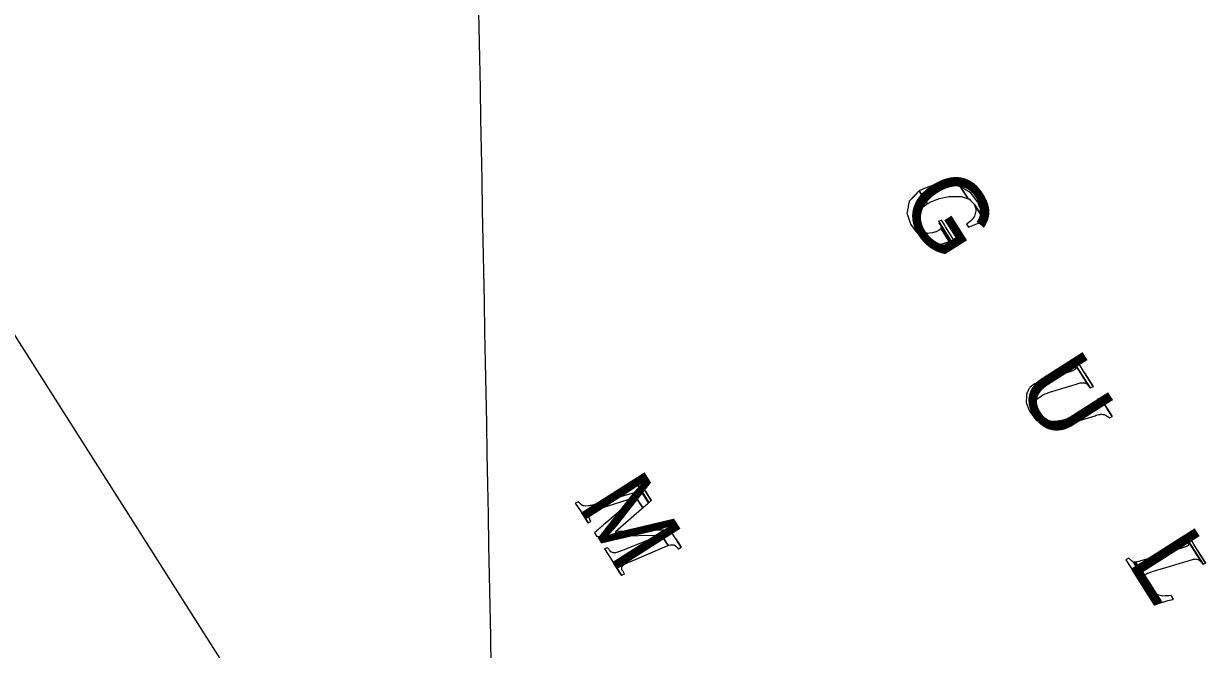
# Model space of a CAD drawing. Extents: x 3962991 to 3983549, y 181631 to 204078.
# Drawn here: x 3972884 to 3974467, y 187232 to 188068 of the extents above; entities that cross this region are included whole.
import ezdxf

# ---------------------------------------------------------------- set-up
doc = ezdxf.new("R2010")
doc.units = 0
for name, color, linetype in [('V-ANNO-MASK', 7, 'Continuous'), ('V-ANNO-MASK2', 7, 'Continuous'), ('V-GRID-FRAM', 7, 'Continuous'), ('V-GRID-MAJR', 7, 'Continuous'), ('V-RIVR-IDEN', 7, 'Continuous')]:
    doc.layers.add(name, color=color, linetype=linetype)

msp = doc.modelspace()

# ---------------------------------------------------------------- linework, layer by layer
at = {"layer": 'V-ANNO-MASK2'}
for points in [[(3974069, 187803.5), (3974070.2, 187799.9), (3974077.6, 187790), (3974084.5, 187783.2), (3974085.5, 187782.4), (3974091.9, 187777.7), (3974077.1, 187800.9), (3974077.1, 187801.3), (3974077, 187802.7), (3974077, 187803.1), (3974076.6, 187812.2), (3974077, 187812.8), (3974078.5, 187814.9), (3974080.7, 187817.8), (3974083.6, 187821.7), (3974083.8, 187821.9), (3974086.9, 187823.9), (3974087.1, 187824), (3974089, 187825.2), (3974089.1, 187825.3), (3974090.4, 187826.1), (3974090.6, 187826.3), (3974091.1, 187826.6), (3974091.4, 187826.8), (3974091.6, 187826.9), (3974091.6, 187826.9), (3974092.1, 187827.3), (3974092.3, 187827.4), (3974092.6, 187827.6), (3974081.6, 187845), (3974081.3, 187844.7), (3974081.1, 187844.5), (3974080.7, 187844.1), (3974080.7, 187844.1), (3974080.5, 187843.9), (3974080.2, 187843.6), (3974079.8, 187843.2), (3974079.7, 187843), (3974078.5, 187841.9), (3974078.5, 187841.8), (3974076.8, 187840.1), (3974076.7, 187839.9), (3974074.1, 187837.2), (3974073.8, 187837), (3974070.6, 187833.7), (3974068.2, 187831.1), (3974067.5, 187827.7), (3974067.3, 187826.8), (3974066.1, 187820.3), (3974066, 187820), (3974065.8, 187819), (3974065.7, 187818.7), (3974065, 187814.7), (3974065.7, 187812.8)], [(3974084.7, 187846.3), (3974081.6, 187845), (3974092.6, 187827.6), (3974095.5, 187829.4), (3974095.5, 187829.5), (3974095.7, 187829.6), (3974095.7, 187829.6), (3974108.6, 187834.5), (3974112.4, 187835.3), (3974121.4, 187837.1), (3974121.4, 187837.1), (3974122.9, 187837.3), (3974129.1, 187837.4), (3974131.2, 187837.4), (3974137.2, 187837.4), (3974138.4, 187837), (3974139, 187836.8), (3974147, 187834.3), (3974136.8, 187850.3), (3974129.3, 187852.1), (3974128.6, 187852.3), (3974127.6, 187852.6), (3974120.4, 187854.3), (3974118.4, 187854.2), (3974112.4, 187853.8), (3974110.9, 187853.7), (3974101.1, 187853), (3974097.7, 187851.6), (3974085, 187846.4), (3974085, 187846.4), (3974084.8, 187846.3)], [(3974137.8, 187849.7), (3974136.8, 187850.3), (3974146.9, 187834.3), (3974147.8, 187834), (3974148.1, 187833.9), (3974150.2, 187831.8), (3974154.8, 187827), (3974155.3, 187826.4), (3974163.7, 187813.2), (3974163.3, 187820.9), (3974162.2, 187823.5), (3974159.6, 187830.2), (3974159.5, 187830.3), (3974150.5, 187842), (3974149.5, 187842.6), (3974142.2, 187847), (3974141.9, 187847.2), (3974139.4, 187848.7), (3974138.3, 187849.4)], [(3974145.8, 187801.2), (3974144.7, 187800.4), (3974147.4, 187796.2), (3974148.7, 187796.8), (3974153.6, 187798.8), (3974155.3, 187799.5), (3974160.1, 187801.4), (3974160.8, 187801.7), (3974161.2, 187801.9), (3974166.3, 187803.9), (3974166.8, 187804.1), (3974167, 187804.2), (3974167.6, 187804.4), (3974163.6, 187810.7), (3974163.8, 187812.8), (3974163.7, 187813.2), (3974155.3, 187826.4), (3974155.4, 187825.9), (3974156.6, 187821.6), (3974157.2, 187819.7), (3974157.4, 187818.9), (3974157.2, 187818.2), (3974155.5, 187810.9), (3974155.2, 187810.6), (3974154.7, 187810), (3974151.3, 187805.7), (3974150.1, 187804.2)], [(3974165.1, 187810.8), (3974163.6, 187810.7), (3974167.6, 187804.4), (3974168.8, 187804.9), (3974172.5, 187806.4), (3974173, 187806.6), (3974173.1, 187806.6), (3974170.1, 187811.2), (3974170, 187811.2), (3974169.4, 187811.2)], [(3974078.8, 187798.6), (3974077.1, 187800.9), (3974091.8, 187777.7), (3974092.3, 187777.3), (3974095.8, 187773.1), (3974096.9, 187771.8), (3974098.6, 187769.2), (3974102.9, 187770.7), (3974103.6, 187771), (3974105.9, 187771.8), (3974109.3, 187772.9), (3974113.6, 187774.5), (3974113.9, 187774.6), (3974113.9, 187774.6), (3974117.5, 187775.8), (3974117.6, 187775.9), (3974120, 187776.5), (3974120.1, 187776.5), (3974122.2, 187776.2), (3974122.6, 187775.9), (3974110.5, 187794.9), (3974110.4, 187794.7), (3974109.5, 187793.2), (3974109.4, 187793.2), (3974107.5, 187791.8), (3974107.4, 187791.7), (3974104, 187790.1), (3974103.7, 187790), (3974099.4, 187788.5), (3974095.5, 187788.1), (3974092.9, 187787.8), (3974091.8, 187788.3), (3974084.6, 187791.2), (3974084.2, 187791.3)], [(3974107.5, 187804.2), (3974107.1, 187804.1), (3974128.6, 187770.3), (3974129, 187770.5), (3974132.1, 187771.8), (3974128.6, 187777.3), (3974121.8, 187788.2), (3974116.7, 187796.5), (3974115.1, 187799.2), (3974111.5, 187805.3), (3974111.2, 187805.2), (3974111.2, 187805.2), (3974111, 187805.2), (3974110.9, 187805.1)], [(3974110.6, 187795.9), (3974110.5, 187794.9), (3974122.6, 187775.9), (3974123.9, 187775.1), (3974125.5, 187773.2), (3974127.8, 187770), (3974127.8, 187770), (3974128.4, 187770.2), (3974128.6, 187770.3), (3974108.3, 187802.2), (3974109.7, 187799.6), (3974110.7, 187796.9), (3974110.7, 187796.8), (3974110.7, 187796.5)], [(3974132.2, 187771.8), (3974128.6, 187777.3), (3974132.1, 187771.8)], [(3974287.1, 187617.8), (3974287, 187617.8), (3974310.1, 187581.5), (3974310.2, 187581.5), (3974313.9, 187583.1), (3974313.9, 187583.1), (3974302.2, 187601.5), (3974291.5, 187619.3), (3974291, 187619.2), (3974291, 187619.1)], [(3974288.3, 187615.4), (3974289.4, 187613.6), (3974307.8, 187584.5), (3974308.4, 187583.8), (3974310, 187581.4), (3974310, 187581.4), (3974310.1, 187581.5), (3974287, 187617.8), (3974288.1, 187615.9)], [(3974227.2, 187554.9), (3974229.1, 187549.7), (3974237.8, 187538.2), (3974240.9, 187536.4), (3974250.2, 187531), (3974238.8, 187549), (3974238.2, 187551.4), (3974238, 187552.1), (3974237.3, 187554.3), (3974236.2, 187558.5), (3974238, 187564.4), (3974238.5, 187565.9), (3974238.9, 187566.9), (3974244.9, 187570.9), (3974246.3, 187571.9), (3974247.5, 187572.7), (3974247.7, 187572.7), (3974258.4, 187576.7), (3974258.6, 187576.7), (3974264.5, 187578.5), (3974266.1, 187579), (3974281, 187583.4), (3974281, 187583.4), (3974290, 187586.1), (3974291.5, 187586.5), (3974291.6, 187586.5), (3974293.3, 187587.1), (3974295.2, 187587.6), (3974296.6, 187588.1), (3974296.7, 187588.1), (3974297.2, 187588.1), (3974298.2, 187588.3), (3974298.6, 187588.3), (3974300, 187588.4), (3974300.7, 187588.4), (3974301.2, 187588.4), (3974301.5, 187588.4), (3974302.9, 187588), (3974303.3, 187588), (3974303.8, 187587.9), (3974304.1, 187587.8), (3974305.4, 187586.9), (3974305.4, 187586.9), (3974305.6, 187586.7), (3974306.3, 187586.3), (3974306.5, 187586.1), (3974307.3, 187585.2), (3974307.9, 187584.5), (3974289.4, 187613.6), (3974289.6, 187613.1), (3974289.8, 187612.4), (3974290, 187611.9), (3974290.5, 187610.6), (3974290.6, 187610.1), (3974290.6, 187608.9), (3974290.6, 187608.6), (3974290.6, 187607.9), (3974290.6, 187607.5), (3974289.9, 187606.7), (3974289.7, 187606.5), (3974289.4, 187606.1), (3974289, 187605.6), (3974287.9, 187605), (3974287.7, 187604.9), (3974286.8, 187604.4), (3974286.4, 187604.2), (3974286.4, 187604.1), (3974285, 187603.6), (3974283.2, 187602.9), (3974281.5, 187602.3), (3974281.5, 187602.3), (3974280, 187601.8), (3974271.1, 187599), (3974256.2, 187594.5), (3974254.7, 187594), (3974248.8, 187592.2), (3974248.6, 187592.1), (3974238, 187588), (3974237.8, 187587.9), (3974236.5, 187587.4), (3974235.1, 187586.3), (3974229.4, 187581.8), (3974228.8, 187581.2), (3974228.1, 187580), (3974225.7, 187575), (3974225, 187573.7), (3974225, 187572.5), (3974224.9, 187572.1), (3974224.9, 187570.9), (3974224.5, 187562.1)], [(3974314.4, 187583.3), (3974302.2, 187601.5), (3974313.9, 187583.1)], [(3974243.8, 187542.5), (3974238.8, 187549), (3974250.2, 187531), (3974251.6, 187530.2), (3974251.8, 187530.3), (3974252.6, 187530.3), (3974254.1, 187530.3), (3974259.7, 187530.4), (3974261, 187530.5), (3974262, 187530.5), (3974270.5, 187530.7), (3974272.2, 187531.2), (3974273.7, 187531.6), (3974273.8, 187531.6), (3974285, 187534.8), (3974285, 187534.8), (3974285.2, 187534.9), (3974291.2, 187536.6), (3974292.8, 187537), (3974307.6, 187541.6), (3974307.6, 187541.6), (3974316.5, 187544.3), (3974318, 187544.8), (3974318, 187544.8), (3974318.1, 187544.8), (3974319.8, 187545.3), (3974321.7, 187545.8), (3974323.4, 187546), (3974323.4, 187546), (3974323.9, 187546.1), (3974325, 187546.2), (3974325.4, 187546.2), (3974326.9, 187546), (3974327.7, 187545.9), (3974328.3, 187545.8), (3974328.6, 187545.8), (3974330.3, 187545), (3974330.7, 187544.9), (3974331.3, 187544.6), (3974331.7, 187544.3), (3974333.1, 187543.4), (3974333.3, 187543.2), (3974334, 187542.8), (3974334.3, 187542.5), (3974334.6, 187542.2), (3974335, 187541.9), (3974335.3, 187541.7), (3974335.3, 187541.6), (3974335.6, 187541.3), (3974335.8, 187541.2), (3974339.2, 187543.3), (3974331.6, 187555.2), (3974330.4, 187557.3), (3974323.7, 187567.8), (3974323.6, 187567.8), (3974319.8, 187566.4), (3974319.7, 187566.4), (3974319.6, 187566.3), (3974319.8, 187566.1), (3974320.3, 187565), (3974320.8, 187563.9), (3974321.1, 187563.2), (3974321.3, 187562.6), (3974321.9, 187561.2), (3974321.9, 187561), (3974322, 187559.6), (3974322.1, 187559.2), (3974322.1, 187558.3), (3974322, 187558), (3974321.5, 187556.8), (3974321.4, 187556.6), (3974321.2, 187556.1), (3974320.8, 187555.7), (3974319.9, 187554.8), (3974319.7, 187554.6), (3974318.9, 187553.9), (3974318.5, 187553.7), (3974318.5, 187553.7), (3974317.2, 187553), (3974315.5, 187552.1), (3974314, 187551.2), (3974314, 187551.2), (3974312.5, 187550.7), (3974303.9, 187547.5), (3974289.1, 187542.7), (3974287.6, 187542.2), (3974281.6, 187540.5), (3974281.4, 187540.5), (3974270.2, 187537.3), (3974270, 187537.3), (3974268.4, 187537.2), (3974266.4, 187537), (3974258.3, 187536.4), (3974257.3, 187536.3), (3974256, 187536.2), (3974248.4, 187539.3), (3974246.3, 187540.2), (3974245.3, 187540.6)], [(3974323.7, 187567.8), (3974323.6, 187567.8), (3974331.6, 187555.2), (3974330.4, 187557.3), (3974324.1, 187568)], [(3974333.3, 187552.7), (3974331.6, 187555.2), (3974339.2, 187543.3), (3974339.2, 187543.4), (3974339.5, 187543.6)], [(3973622.1, 187427.4), (3973621.8, 187427.3), (3973629.6, 187415.6), (3973630.4, 187414.3), (3973638.9, 187401), (3973642.6, 187402.9), (3973641.9, 187404), (3973641.8, 187404.4), (3973641.3, 187405.5), (3973641.1, 187406), (3973640.8, 187406.6), (3973640.8, 187406.7), (3973640.7, 187407.3), (3973640.7, 187407.3), (3973640.5, 187408.1), (3973640.1, 187409.6), (3973640.1, 187409.8), (3973640.1, 187410.7), (3973640.2, 187411.4), (3973640.2, 187412.2), (3973640.3, 187412.4), (3973641.3, 187414.1), (3973641.4, 187414.3), (3973641.6, 187414.4), (3973643.8, 187415.8), (3973644.3, 187416.1), (3973645, 187416.6), (3973646.2, 187417), (3973647.3, 187417.5), (3973647.2, 187417.5), (3973647.5, 187417.6), (3973650.2, 187418.7), (3973656, 187420.6), (3973700.8, 187434.9), (3973700.8, 187434.9), (3973701.2, 187435.1), (3973702.7, 187435.5), (3973711.9, 187421.1), (3973713.1, 187422.1), (3973713.1, 187422.2), (3973714, 187422.9), (3973715.5, 187424.2), (3973716.6, 187425.2), (3973717.1, 187425.6), (3973717.1, 187425.6), (3973718.3, 187426.6), (3973718.3, 187426.6), (3973718.4, 187426.7), (3973719.3, 187427.5), (3973719.5, 187427.7), (3973707, 187447.3), (3973707, 187446.9), (3973706.7, 187445), (3973706.7, 187444.8), (3973705.6, 187443.7), (3973705, 187443.4), (3973703.7, 187442.6), (3973701.9, 187441.8), (3973700.9, 187441.3), (3973699.4, 187440.8), (3973697.9, 187440.3), (3973697.5, 187440.2), (3973651.9, 187427), (3973646, 187425.2), (3973643.2, 187424.4), (3973642.9, 187424.3), (3973641.7, 187424.1), (3973640.4, 187423.8), (3973639.5, 187423.6), (3973638.8, 187423.6), (3973636, 187423.2), (3973635.8, 187423.3), (3973635.5, 187423.3), (3973633.2, 187423.6), (3973632.8, 187423.8), (3973632.1, 187424.1), (3973631.4, 187424.4), (3973630.6, 187424.8), (3973630.3, 187425.1), (3973628.9, 187426.2), (3973628.2, 187426.9), (3973627.7, 187427.3), (3973627.5, 187427.6), (3973627.1, 187428), (3973626.8, 187428.4), (3973626, 187429.2), (3973626, 187429.1), (3973622.1, 187427.4)], [(3973704, 187454), (3973704.9, 187452.3), (3973720.2, 187428.3), (3973720.3, 187428.3), (3973720.3, 187428.3), (3973723.4, 187431), (3973723.4, 187431.1), (3973715.6, 187443.4), (3973708.3, 187455.5), (3973708, 187455.4), (3973707.9, 187455.4)], [(3973706.3, 187449.4), (3973707, 187447.3), (3973719.5, 187427.7), (3973719.9, 187428), (3973719.9, 187428.1), (3973720, 187428.1), (3973720.2, 187428.3), (3973704.9, 187452.3), (3973706.2, 187449.8), (3973706.2, 187449.6)], [(3973723.7, 187431.3), (3973715.6, 187443.4), (3973723.4, 187431.1), (3973723.7, 187431.3)], [(3973650.5, 187390.6), (3973647.3, 187387.8), (3973650.4, 187382.8), (3973655.4, 187382.9), (3973655.5, 187382.9), (3973655.7, 187382.9), (3973655.8, 187382.9), (3973655.9, 187382.9), (3973656, 187382.9), (3973656.2, 187382.9), (3973656.5, 187382.9), (3973657.1, 187382.9), (3973657.2, 187382.9), (3973657.8, 187382.9), (3973658.3, 187383), (3973658.3, 187383), (3973658.8, 187383), (3973659, 187383), (3973661.1, 187383), (3973661.3, 187383), (3973661.6, 187383), (3973664.6, 187383.1), (3973664.6, 187383.1), (3973665.3, 187383.1), (3973666.3, 187383.1), (3973666.3, 187383.2), (3973667.7, 187383.2), (3973669.1, 187383.2), (3973669.4, 187383.2), (3973672.7, 187383.3), (3973679.6, 187383.5), (3973675.6, 187389.7), (3973710.4, 187419.8), (3973710.7, 187420.1), (3973711.9, 187421.1), (3973702.7, 187435.5), (3973701.6, 187434.5), (3973701.2, 187434.3), (3973666.4, 187404.2), (3973661.8, 187400.3), (3973659.7, 187398.5), (3973659.5, 187398.3), (3973658.6, 187397.5), (3973657.6, 187396.7), (3973657, 187396.2), (3973656.5, 187395.8), (3973654.5, 187394.1), (3973654.4, 187393.9), (3973654.2, 187393.8), (3973652.9, 187392.6), (3973652.7, 187392.5), (3973652.4, 187392.2), (3973652, 187391.9), (3973651.7, 187391.6), (3973651.6, 187391.5), (3973651.2, 187391.2), (3973651, 187391), (3973650.9, 187390.9), (3973650.8, 187390.9), (3973650.8, 187390.8), (3973650.7, 187390.7), (3973650.5, 187390.6)], [(3973637.9, 187402), (3973638.6, 187400.8), (3973638.6, 187400.8), (3973638.9, 187401), (3973638.9, 187401), (3973630.4, 187414.3), (3973631.2, 187413)], [(3973660.8, 187366.4), (3973660.6, 187366.3), (3973668.8, 187353.8), (3973673.4, 187346.9), (3973683.4, 187331.2), (3973687.3, 187332.7), (3973687.4, 187332.7), (3973686, 187335.3), (3973685.6, 187336), (3973685.2, 187336.8), (3973685, 187337.3), (3973684.2, 187338.8), (3973684.1, 187339.5), (3973683.9, 187340.7), (3973683.9, 187341), (3973683.7, 187342.2), (3973684, 187342.5), (3973684.3, 187342.9), (3973684.3, 187342.9), (3973684.4, 187343), (3973685.6, 187344.5), (3973685.8, 187344.6), (3973685.9, 187344.7), (3973688.1, 187346.2), (3973688.6, 187346.4), (3973689.4, 187346.8), (3973690.5, 187347.4), (3973691.6, 187347.8), (3973691.8, 187347.9), (3973694.4, 187349), (3973700, 187351.4), (3973742.5, 187369.3), (3973742.9, 187369.5), (3973745.8, 187370.6), (3973736.8, 187384.8), (3973733.9, 187383.7), (3973733.5, 187383.5), (3973690.3, 187366.5), (3973684.7, 187364.3), (3973682.1, 187363.3), (3973681.8, 187363.2), (3973680.7, 187362.8), (3973679.5, 187362.4), (3973678.7, 187362.1), (3973678.1, 187361.9), (3973675.6, 187361), (3973675.4, 187361), (3973675.1, 187360.9), (3973673, 187360.9), (3973672.8, 187360.9), (3973672.3, 187360.9), (3973671.5, 187361.3), (3973670.6, 187361.8), (3973670.4, 187361.9), (3973669.5, 187362.4), (3973668.4, 187363.6), (3973667.7, 187364.5), (3973667.4, 187364.7), (3973667.1, 187365.2), (3973666.4, 187366.1), (3973665, 187367.8), (3973665, 187367.8), (3973661, 187366.5)], [(3973728.6, 187391.2), (3973675.6, 187389.7), (3973679.6, 187383.5), (3973732.8, 187384.7), (3973733.3, 187384.7), (3973736.8, 187384.8), (3973745.8, 187370.6), (3973745.8, 187370.7), (3973745.8, 187370.7), (3973746.9, 187371.1), (3973748.9, 187371.6), (3973750.5, 187371.9), (3973751.3, 187371.8), (3973753.4, 187371.5), (3973753.5, 187371.5), (3973755.7, 187370.3), (3973756.5, 187369.6), (3973758, 187368.1), (3973759.2, 187366.3), (3973759.3, 187366.3), (3973759.5, 187366.4), (3973759.6, 187366.5), (3973763.2, 187368.5), (3973756, 187379.7), (3973753.6, 187383.7), (3973748.7, 187391.7), (3973748.5, 187391.7), (3973748.4, 187391.7), (3973743.6, 187391.6), (3973743.5, 187391.6), (3973743.2, 187391.5), (3973743.2, 187391.6), (3973743.1, 187391.5), (3973742.5, 187391.5), (3973742.2, 187391.5), (3973740.8, 187391.5), (3973740.6, 187391.5), (3973738.8, 187391.4), (3973738.1, 187391.4), (3973736.3, 187391.4), (3973734, 187391.3), (3973732.7, 187391.3), (3973732.6, 187391.3), (3973729.1, 187391.2)], [(3974441.5, 187383.1), (3974437.9, 187382), (3974460.8, 187346), (3974464.3, 187347.3), (3974453.1, 187364.9), (3974442.1, 187383.3)], [(3974437.9, 187382), (3974438.9, 187380.3), (3974460.8, 187346), (3974460.8, 187346)], [(3974440.2, 187377.7), (3974440.3, 187377.5), (3974458.9, 187348.3), (3974459, 187348.2), (3974460.5, 187345.9), (3974460.8, 187346), (3974438.9, 187380.3), (3974440.1, 187378)], [(3973758.1, 187376.6), (3973756, 187379.7), (3973763.2, 187368.5), (3973763.2, 187368.5), (3973763.5, 187368.6)], [(3974371, 187348.5), (3974370.5, 187348.4), (3974382.5, 187329.4), (3974382.8, 187330), (3974383.6, 187331.4), (3974384.3, 187331.9), (3974385.4, 187332.8), (3974386.5, 187333.6), (3974387.4, 187334), (3974389.7, 187334.9), (3974392.1, 187335.7), (3974394.4, 187336.4), (3974445.2, 187351.8), (3974445.2, 187351.8), (3974447.9, 187352.4), (3974448.8, 187352.7), (3974450.4, 187352.7), (3974452, 187352.8), (3974452.2, 187352.7), (3974454.2, 187352.2), (3974454.9, 187352), (3974456.8, 187350.5), (3974457, 187350.4), (3974458.9, 187348.3), (3974440.3, 187377.5), (3974441.3, 187375), (3974441.5, 187374.5), (3974441.5, 187373.1), (3974441.5, 187372.2), (3974440.6, 187370.9), (3974440.5, 187370.8), (3974439.4, 187370), (3974438.1, 187369.4), (3974437.3, 187369), (3974434.9, 187368), (3974434.9, 187368), (3974384.3, 187352.3), (3974382, 187351.6), (3974379.6, 187350.8), (3974377.2, 187350.1), (3974376.3, 187349.8), (3974374.9, 187349.3), (3974373.4, 187349), (3974372.5, 187348.8)], [(3974464.7, 187347.5), (3974453.1, 187364.9), (3974464.3, 187347.3)], [(3974357.7, 187351.7), (3974357.5, 187351.6), (3974367.5, 187336.5), (3974396, 187291.6), (3974400.5, 187293), (3974400.4, 187293), (3974400.8, 187293.1), (3974401.4, 187293.3), (3974385.4, 187318.5), (3974384.8, 187319.7), (3974384.8, 187319.7), (3974382.2, 187324.9), (3974382.2, 187325.1), (3974382.2, 187326), (3974367.9, 187348.5), (3974367, 187349.1), (3974366.8, 187349.2), (3974365.6, 187349.9), (3974365.1, 187350.3), (3974363.4, 187352), (3974361.8, 187353.9)], [(3973682.3, 187332.1), (3973683, 187331.1), (3973683, 187331.1), (3973683.3, 187331.2), (3973683.4, 187331.2), (3973673.4, 187346.9), (3973676.6, 187341.6)], [(3974367.5, 187336.5), (3974395.7, 187291.5), (3974396, 187291.6)], [(3974369.6, 187348.4), (3974367.9, 187348.5), (3974382.2, 187326), (3974382.2, 187328.7), (3974382.5, 187329.4), (3974370.5, 187348.4)], [(3974386.5, 187317), (3974385.4, 187318.5), (3974401.4, 187293.3), (3974401.5, 187293.4), (3974402.2, 187293.6), (3974402.2, 187293.6), (3974402.2, 187293.6), (3974402.8, 187293.8), (3974404.1, 187294.2), (3974404.8, 187294.4), (3974405.3, 187294.6), (3974405.3, 187294.6), (3974406.8, 187295), (3974407.6, 187295.3), (3974409, 187295.7), (3974410.4, 187296.1), (3974411.3, 187296.4), (3974411.3, 187296.4), (3974413.7, 187297.1), (3974416.2, 187297.8), (3974416.2, 187297.8), (3974418.5, 187298.4), (3974421.2, 187299.2), (3974418.3, 187303.8), (3974415.3, 187303.5), (3974412.6, 187303.4), (3974409.7, 187303.4), (3974406.9, 187303.3), (3974405.6, 187303.6), (3974403.7, 187304), (3974401.7, 187304.4), (3974400.6, 187304.7), (3974398.6, 187305.1), (3974397.5, 187305.9), (3974396, 187307), (3974392.9, 187309.3), (3974391.8, 187310.1), (3974391.3, 187310.7)]]:
    msp.add_lwpolyline(points, close=True, dxfattribs=at)
at = {"layer": 'V-GRID-FRAM'}
msp.add_lwpolyline([(3973881.1, 201670.7), (3982001.8, 189003.7), (3974929.2, 184418.3), (3966825.4, 197159.8), (3973881.1, 201670.7)], dxfattribs=at)
at = {"layer": 'V-GRID-MAJR'}
msp.add_spline([(3973536.4, 185784.1), (3973487.2, 188388.7), (3973372.6, 194448.6), (3973258, 200508.6), (3973228.2, 202082.7)], degree=3, dxfattribs=at)

# ---------------------------------------------------------------- texts
at = {"layer": 'V-ANNO-MASK'}
for s, p in [('G', (3974052.8, 187831.2)), ('U', (3974209.9, 187584.3)), ('M', (3973624.1, 187424.3)), ('L', (3974359.3, 187349.4))]:
    msp.add_text(s, height=100, rotation=302.457, dxfattribs=at).set_placement(p)
at = {"layer": 'V-RIVR-IDEN'}
for s, p in [('G', (3974052.8, 187831.2)), ('U', (3974209.9, 187584.3)), ('M', (3973624.1, 187424.3)), ('L', (3974359.3, 187349.4))]:
    msp.add_text(s, height=100, rotation=302.457, dxfattribs=at).set_placement(p)

doc.saveas('drawing.dxf')
